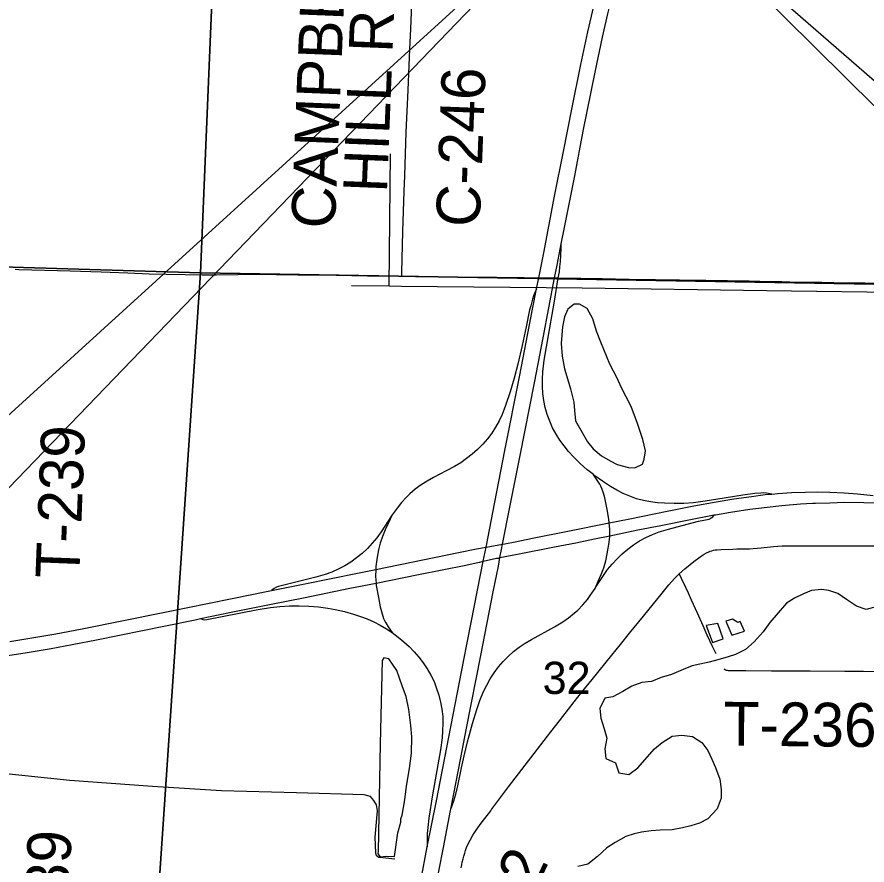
# Model space of a CAD drawing. Extents: x -59 to 43, y 0 to 22.
# Drawn here: x 25.998 to 27.1, y 15.494 to 16.594 of the extents above; entities that cross this region are included whole.
import ezdxf

# ---------------------------------------------------------------- set-up
doc = ezdxf.new("R2010")
doc.units = 0
for name, color, linetype in [('BR_P_Gen_Text', 7, 'Continuous'), ('GM_X_County_Road', 7, 'Continuous'), ('GM_X_County_Road_Text', 7, 'Continuous'), ('GM_X_Interchange_Ramps', 7, 'Continuous'), ('GM_X_Interstate_Route', 7, 'Continuous'), ('GM_X_Major_River', 7, 'Continuous'), ('GM_X_Minor_Lake', 7, 'Continuous'), ('GM_X_Minor_River', 7, 'Continuous'), ('GM_X_Section', 7, 'Continuous'), ('GM_X_Section_Text', 7, 'Continuous'), ('GM_X_Township_Road', 7, 'Continuous'), ('GM_X_Township_Road_Text', 7, 'Continuous'), ('GM_X_US_Route', 7, 'Continuous')]:
    doc.layers.add(name, color=color, linetype=linetype)

msp = doc.modelspace()

# ---------------------------------------------------------------- linework, layer by layer
at = {"layer": 'BR_P_Gen_Text'}
for points in [[(26.7273, 16.7521), (23.5585, 13.8664), (23.9482, 13.8664)], [(26.8361, 16.7501), (30.1526, 13.8664), (29.75, 13.8664)]]:
    msp.add_lwpolyline(points, close=True, dxfattribs=at)
at = {"layer": 'GM_X_County_Road'}
msp.add_line((25.9954, 16.2669), (26.0005, 16.2667), dxfattribs=at)
for points in [[(26.4971, 16.2578), (26.4972, 16.2627), (26.4982, 16.3159), (26.5002, 16.3681), (26.5009, 16.3879), (26.5013, 16.4022), (26.5019, 16.4165), (26.5028, 16.4445), (26.5051, 16.4991), (26.5064, 16.5314), (26.5074, 16.5525), (26.5085, 16.5786), (26.5113, 16.6444), (26.5126, 16.6724), (26.5133, 16.6897), (26.5147, 16.7251), (26.5158, 16.7468), (26.516, 16.7521), (26.5163, 16.7562)], [(26.0005, 16.2667), (26.0171, 16.266), (26.0668, 16.2647), (26.1073, 16.2633), (26.1415, 16.2622), (26.1694, 16.2611), (26.1912, 16.2605), (26.2161, 16.2599), (26.2379, 16.2594), (26.2565, 16.2595), (26.2845, 16.2601), (26.3032, 16.2603), (26.3343, 16.2599), (26.3622, 16.2598), (26.412, 16.2592), (26.4524, 16.2584), (26.4971, 16.2578)], [(26.4971, 16.2578), (26.5147, 16.2576), (26.5427, 16.2575), (26.5675, 16.2571), (26.6204, 16.2565), (26.6483, 16.2561), (26.6555, 16.256)], [(26.6555, 16.256), (26.6747, 16.2559), (26.6952, 16.2556), (26.7, 16.2556), (26.7121, 16.2554)], [(26.7121, 16.2554), (26.7292, 16.2552), (26.75, 16.2548)], [(26.75, 16.2548), (26.7569, 16.2547), (26.7918, 16.2542), (26.826, 16.2536), (26.8571, 16.2531), (26.8913, 16.2525), (26.9473, 16.2517), (26.9753, 16.2511), (26.9897, 16.2508), (27.0002, 16.2507), (27.0418, 16.25), (27.0728, 16.2492), (27.0976, 16.2491), (27.1254, 16.2487), (27.1564, 16.2484), (27.2188, 16.2477)]]:
    msp.add_lwpolyline(points, dxfattribs=at)
at = {"layer": 'GM_X_Interchange_Ramps'}
for points in [[(26.7, 16.2556), (26.7013, 16.2635), (26.7021, 16.2702), (26.7027, 16.2768), (26.7032, 16.2847), (26.7037, 16.2944), (26.7038, 16.3)], [(26.9771, 15.9752), (26.9698, 15.9764), (26.9666, 15.9766), (26.9628, 15.9765), (26.9548, 15.9759), (26.9394, 15.9739), (26.9149, 15.97), (26.8904, 15.9659), (26.8751, 15.9639), (26.8627, 15.963), (26.8503, 15.9629), (26.8379, 15.9632), (26.8287, 15.9638), (26.8194, 15.9649), (26.8103, 15.9667), (26.8013, 15.9691), (26.7926, 15.9723), (26.7841, 15.976), (26.7758, 15.9802), (26.7677, 15.9849), (26.7574, 15.9917), (26.7473, 15.999), (26.745, 16.0008), (26.7376, 16.0067), (26.7283, 16.0149), (26.7195, 16.0236), (26.7133, 16.0305), (26.7074, 16.0377), (26.7019, 16.0452), (26.697, 16.0531), (26.6926, 16.0613), (26.6888, 16.0698), (26.6856, 16.0785), (26.6831, 16.0874), (26.6812, 16.0965), (26.6799, 16.1058), (26.6793, 16.115), (26.6793, 16.1243), (26.6799, 16.1336), (26.6818, 16.149), (26.686, 16.1734), (26.6951, 16.2253), (26.7, 16.2556)], [(26.6718, 16.2413), (26.6692, 16.2356), (26.6679, 16.2322), (26.6666, 16.2281), (26.6642, 16.2196), (26.6628, 16.2144), (26.6582, 16.1921), (26.6533, 16.1678), (26.6476, 16.1436), (26.6429, 16.1256), (26.6375, 16.1077), (26.6315, 16.0901), (26.627, 16.0785), (26.6232, 16.0701), (26.6187, 16.0619), (26.6136, 16.0541), (26.608, 16.0467), (26.6019, 16.0397), (26.5953, 16.0331), (26.5883, 16.0269), (26.581, 16.0211), (26.5734, 16.0158), (26.5655, 16.0109), (26.5545, 16.0051), (26.5379, 15.9967), (26.5298, 15.9921), (26.522, 15.987), (26.5145, 15.9815), (26.5074, 15.9755), (26.5029, 15.9712), (26.4967, 15.9643), (26.491, 15.957), (26.4847, 15.9482), (26.4838, 15.9468), (26.4701, 15.9261), (26.4646, 15.9186), (26.4587, 15.9114), (26.4524, 15.9046), (26.4456, 15.8982), (26.4384, 15.8923), (26.4308, 15.8869), (26.4229, 15.882), (26.4146, 15.8777), (26.4061, 15.8739), (26.3974, 15.8708), (26.3855, 15.8672), (26.3614, 15.8612), (26.3372, 15.8554), (26.3347, 15.8544), (26.3316, 15.8528), (26.328, 15.85)], [(26.7666, 15.9211), (26.767, 15.9295), (26.7661, 15.9378), (26.7656, 15.9426), (26.7634, 15.955), (26.7603, 15.9704), (26.7587, 15.9765), (26.7566, 15.9824), (26.7553, 15.9853), (26.7538, 15.988), (26.7502, 15.9932), (26.745, 16.0008)], [(26.4847, 15.9482), (26.4793, 15.9371), (26.4753, 15.9288), (26.4718, 15.9203), (26.469, 15.9115), (26.4668, 15.9026), (26.4651, 15.8935), (26.4634, 15.8813), (26.4633, 15.8775), (26.463, 15.8683), (26.4636, 15.8597)], [(26.5606, 15.5662), (26.5645, 15.5771), (26.5658, 15.5813), (26.567, 15.5857), (26.5697, 15.5968), (26.5746, 15.6199), (26.5779, 15.6356), (26.5823, 15.6537), (26.5889, 15.6777), (26.5943, 15.6956), (26.5984, 15.7074), (26.6031, 15.7189), (26.6071, 15.7273), (26.6116, 15.7355), (26.6167, 15.7433), (26.6222, 15.7508), (26.6283, 15.7579), (26.6349, 15.7646), (26.6419, 15.7707), (26.6493, 15.7764), (26.657, 15.7816), (26.665, 15.7864), (26.695, 15.8029), (26.7057, 15.8094), (26.7133, 15.8147), (26.7206, 15.8205), (26.7253, 15.8247), (26.7318, 15.8314), (26.7378, 15.8385), (26.7415, 15.8435), (26.7476, 15.8527), (26.7484, 15.8538), (26.7585, 15.8696), (26.7639, 15.8772), (26.7698, 15.8844), (26.7761, 15.8913), (26.7829, 15.8978), (26.79, 15.9038), (26.7975, 15.9094), (26.8054, 15.9144), (26.8136, 15.9188), (26.8221, 15.9226), (26.8308, 15.926), (26.8427, 15.9297), (26.8607, 15.9346), (26.8819, 15.9398), (26.8956, 15.9428), (26.8973, 15.9435), (26.8984, 15.9442), (26.9002, 15.9457), (26.902, 15.9481)], [(26.7476, 15.8527), (26.7517, 15.862), (26.7555, 15.8708), (26.7588, 15.8794), (26.7614, 15.8884), (26.7634, 15.8975), (26.7655, 15.9099), (26.7666, 15.9195), (26.7666, 15.9211)], [(26.4636, 15.8597), (26.4639, 15.8564), (26.4666, 15.841), (26.4691, 15.8288), (26.4714, 15.8197), (26.4734, 15.8138), (26.4746, 15.811), (26.4761, 15.8082), (26.4795, 15.803), (26.4844, 15.7954)], [(26.2358, 15.8136), (26.2389, 15.8123), (26.2415, 15.812), (26.2441, 15.8124), (26.3082, 15.825), (26.3266, 15.8279), (26.339, 15.8293), (26.3515, 15.83), (26.3639, 15.8301), (26.3764, 15.8297), (26.3888, 15.8287), (26.4012, 15.827), (26.4104, 15.8254), (26.4225, 15.8226), (26.4345, 15.8193), (26.4434, 15.8164), (26.4521, 15.8131), (26.4607, 15.8092), (26.469, 15.805), (26.477, 15.8002), (26.4844, 15.7954), (26.4924, 15.7895), (26.4996, 15.7836), (26.5065, 15.7773), (26.5129, 15.7705), (26.519, 15.7634), (26.5247, 15.756), (26.53, 15.7483), (26.5346, 15.7402), (26.5388, 15.7318), (26.5422, 15.7231), (26.5452, 15.7142), (26.5474, 15.7052), (26.549, 15.696), (26.55, 15.6867), (26.5503, 15.6773), (26.5499, 15.668), (26.5492, 15.6587), (26.547, 15.6433), (26.5369, 15.5849), (26.5321, 15.5547), (26.5308, 15.5426), (26.5301, 15.5347), (26.53, 15.5279), (26.5301, 15.5175)]]:
    msp.add_lwpolyline(points, dxfattribs=at)
at = {"layer": 'GM_X_Interstate_Route'}
for points in [[(26.7038, 16.3), (26.7079, 16.3211), (26.7213, 16.3882), (26.7323, 16.4462), (26.7476, 16.5224), (26.7572, 16.5681), (26.7642, 16.5984), (26.7724, 16.6316), (26.7805, 16.6616), (26.7992, 16.7274), (26.8026, 16.7393), (26.8049, 16.7469)], [(26.6718, 16.2413), (26.6747, 16.2559), (26.6811, 16.2883), (26.6952, 16.3616), (26.7067, 16.4195), (26.7174, 16.4745), (26.729, 16.5324), (26.7383, 16.5749), (26.7461, 16.6082)], [(26.6952, 16.2556), (26.6984, 16.2723), (26.7038, 16.3)], [(26.6222, 15.8818), (26.6243, 15.8927), (26.6263, 15.9032), (26.6277, 15.9102), (26.6372, 15.9581), (26.6503, 16.0252), (26.6689, 16.1197), (26.6803, 16.1777), (26.6952, 16.2556)], [(26.5301, 15.5175), (26.5418, 15.5773), (26.5579, 15.6596), (26.5776, 15.7603), (26.5913, 15.8305), (26.6026, 15.888), (26.6062, 15.9062), (26.6176, 15.9647), (26.6307, 16.0318), (26.6499, 16.1294), (26.6583, 16.1721), (26.6666, 16.2149), (26.6718, 16.2413)], [(26.551, 15.5166), (26.5603, 15.5645), (26.5606, 15.5662), (26.5709, 15.6195), (26.5808, 15.6714), (26.5996, 15.7659), (26.6157, 15.8483), (26.6222, 15.8818)], [(26.4474, 15.0879), (26.448, 15.092), (26.4521, 15.1165), (26.4637, 15.1776), (26.4776, 15.2489), (26.4839, 15.2813), (26.5036, 15.382), (26.5215, 15.4735), (26.5301, 15.5175)], [(26.5402, 15.4616), (26.5456, 15.4882), (26.551, 15.5166)]]:
    msp.add_lwpolyline(points, dxfattribs=at)
at = {"layer": 'GM_X_Major_River'}
for points in [[(27.1087, 15.8281), (27.0991, 15.8256), (27.0867, 15.8296), (27.0739, 15.8382), (27.0623, 15.846), (27.0509, 15.85), (27.0415, 15.8513), (27.0285, 15.8501), (27.0178, 15.8457), (27.0063, 15.8402), (26.9959, 15.8335), (26.9851, 15.8212), (26.9742, 15.8085), (26.9656, 15.7965), (26.954, 15.7834), (26.9428, 15.7733), (26.9297, 15.7671), (26.9202, 15.7642), (26.9068, 15.7599), (26.8954, 15.7571), (26.8835, 15.7543), (26.8736, 15.7525), (26.8617, 15.7474), (26.8468, 15.7409), (26.8334, 15.7373), (26.8208, 15.7322)], [(26.8208, 15.7322), (26.8082, 15.7305), (26.7952, 15.7258), (26.7837, 15.7192), (26.7707, 15.7122), (26.7604, 15.7105), (26.7537, 15.6969), (26.755, 15.6844), (26.7593, 15.6706), (26.7629, 15.6584), (26.7603, 15.6448), (26.7616, 15.6322), (26.7741, 15.6263), (26.7784, 15.6133), (26.7913, 15.6112), (26.8032, 15.6201), (26.8249, 15.6448), (26.8346, 15.653), (26.8476, 15.6611), (26.8602, 15.6624), (26.8739, 15.6606), (26.8863, 15.6528), (26.894, 15.6424), (26.8992, 15.6313), (26.9039, 15.6206), (26.9093, 15.6053), (26.911, 15.5919), (26.9112, 15.5805), (26.906, 15.5666), (26.894, 15.5539), (26.8829, 15.548), (26.8718, 15.5448), (26.8611, 15.5423), (26.8477, 15.5395), (26.8321, 15.539), (26.8203, 15.5381), (26.8078, 15.5364), (26.7982, 15.5343), (26.7875, 15.5307), (26.7737, 15.523), (26.7629, 15.516), (26.7506, 15.5048), (26.7382, 15.4951), (26.7253, 15.4919)]]:
    msp.add_lwpolyline(points, dxfattribs=at)
at = {"layer": 'GM_X_Minor_Lake'}
for p, q in [((26.7224, 16.0702), (26.7379, 16.0428)), ((26.9172, 15.8103), (26.9251, 15.7922)), ((26.9069, 15.8074), (26.8917, 15.8046))]:
    msp.add_line(p, q, dxfattribs=at)
for points in [[(26.7379, 16.0428), (26.7453, 16.0337), (26.7561, 16.0247), (26.7674, 16.0181), (26.7761, 16.0137), (26.7908, 16.0097), (26.7992, 16.0092), (26.8092, 16.0139), (26.8115, 16.0203), (26.8129, 16.0313), (26.8097, 16.0458), (26.8025, 16.0668), (26.7945, 16.0886), (26.7879, 16.1013), (26.7821, 16.1132), (26.7762, 16.1254), (26.7666, 16.1435), (26.755, 16.1722), (26.7496, 16.1867), (26.7449, 16.2027), (26.7375, 16.2158), (26.7274, 16.2217), (26.7205, 16.2214), (26.7124, 16.2151), (26.7081, 16.2053), (26.7056, 16.192), (26.7037, 16.1704), (26.7049, 16.1541), (26.708, 16.1377), (26.7123, 16.1235), (26.7159, 16.1117), (26.7202, 16.0945), (26.7211, 16.0835), (26.7224, 16.0702)], [(26.9251, 15.7922), (26.9413, 15.7973), (26.9358, 15.8099), (26.9328, 15.8085), (26.926, 15.8128), (26.9172, 15.8103)], [(26.8917, 15.8046), (26.8998, 15.7828), (26.9139, 15.7872), (26.9069, 15.8074)], [(26.4904, 15.7462), (26.4851, 15.7546), (26.4802, 15.7614), (26.4737, 15.7626), (26.4714, 15.7592), (26.4688, 15.6509), (26.4665, 15.5119), (26.4661, 15.5085), (26.4688, 15.5046), (26.4771, 15.5054), (26.4874, 15.505)], [(26.4874, 15.505), (26.4919, 15.5356), (26.4957, 15.5493), (26.4957, 15.5536), (26.4973, 15.5585), (26.5011, 15.5784), (26.5033, 15.5962), (26.5068, 15.6189), (26.5094, 15.639), (26.5098, 15.6603), (26.5089, 15.6747), (26.5062, 15.6957), (26.5027, 15.7125), (26.4977, 15.7251), (26.4934, 15.7374), (26.4904, 15.7462)]]:
    msp.add_lwpolyline(points, dxfattribs=at)
at = {"layer": 'GM_X_Minor_River'}
for points in [[(26.4805, 16.2447), (26.4822, 16.4164)], [(26.4968, 16.2443), (26.4805, 16.2447), (26.4316, 16.2452)], [(27.6072, 16.2249), (27.5149, 16.2285), (27.2969, 16.2339), (27.1651, 16.2362), (26.9698, 16.239), (26.7308, 16.2425), (26.4968, 16.2443)], [(26.4881, 15.5016), (26.4722, 15.5031), (26.4672, 15.5035), (26.4642, 15.5058), (26.4635, 15.5096), (26.4624, 15.5301), (26.4655, 15.5643), (26.4644, 15.5719), (26.4606, 15.5776), (26.4565, 15.5826), (26.4481, 15.5849), (26.3605, 15.5874), (26.263, 15.5903), (26.1735, 15.5959), (26.0665, 15.6035), (25.9796, 15.6128)]]:
    msp.add_lwpolyline(points, dxfattribs=at)
at = {"layer": 'GM_X_Section'}
for points in [[(25.1878, 17.2935), (26.2782, 17.275), (26.2361, 16.2622), (25.1744, 16.294), (25.173, 16.308)], [(27.273, 17.253), (27.2374, 16.2454), (26.2361, 16.2622), (26.2782, 17.275)], [(25.1744, 16.294), (26.2361, 16.2622), (26.1685, 15.2661), (25.1667, 15.3001)], [(26.2361, 16.2622), (27.2374, 16.2454), (27.2021, 15.2348), (26.2022, 15.2649), (26.1685, 15.2661)]]:
    msp.add_lwpolyline(points, close=True, dxfattribs=at)
at = {"layer": 'GM_X_Township_Road'}
for points in [[(26.9315, 15.9039), (26.9425, 15.904), (26.948, 15.9042), (26.9526, 15.9044), (26.9631, 15.9053), (26.9792, 15.907), (26.9903, 15.9078), (27.0034, 15.9081), (27.0469, 15.9081), (27.0979, 15.9081), (27.152, 15.9081)], [(26.8567, 15.8716), (26.8639, 15.878), (26.8759, 15.8878), (26.8839, 15.8937), (26.8891, 15.8972), (26.8923, 15.899), (26.8952, 15.9003), (26.897, 15.901), (26.899, 15.9017), (26.9011, 15.9023), (26.9033, 15.9027), (26.9062, 15.903), (26.9113, 15.9033), (26.9265, 15.9038), (26.9315, 15.9039)], [(26.6135, 15.566), (26.6355, 15.5952), (26.6904, 15.6667), (26.7015, 15.6809), (26.7205, 15.7055), (26.7302, 15.7176), (26.744, 15.7345), (26.7692, 15.7661), (26.7805, 15.7801), (26.7923, 15.7946), (26.8105, 15.8167), (26.8346, 15.8467), (26.8433, 15.8573), (26.8508, 15.8656), (26.8542, 15.8691), (26.8567, 15.8716)], [(26.8567, 15.8716), (26.8594, 15.8662), (26.865, 15.8544), (26.8683, 15.847), (26.8721, 15.8379), (26.8799, 15.821), (26.8874, 15.8046), (26.8926, 15.7927), (26.899, 15.7786), (26.9041, 15.7681)], [(26.9145, 15.7484), (26.9155, 15.7478), (26.9166, 15.7473), (26.9176, 15.7469), (26.9188, 15.7466), (26.9202, 15.7464), (26.9219, 15.7463), (26.9287, 15.7462), (26.9432, 15.7462), (26.9766, 15.746), (27.0266, 15.7457), (27.0717, 15.7455), (27.0959, 15.7453), (27.1251, 15.7451), (27.1869, 15.7445), (27.2147, 15.7442), (27.2495, 15.7436), (27.2712, 15.7429), (27.2805, 15.7425), (27.2894, 15.7422), (27.319, 15.7418), (27.4098, 15.7395), (27.4626, 15.738), (27.4747, 15.7376)], [(26.5742, 15.4903), (26.5748, 15.494), (26.5755, 15.4976), (26.5764, 15.5017), (26.5774, 15.5055), (26.5786, 15.5092), (26.5797, 15.5126), (26.5811, 15.5164), (26.5824, 15.5195), (26.5856, 15.5262), (26.5893, 15.5327), (26.5934, 15.539), (26.6, 15.548), (26.6123, 15.5644), (26.6135, 15.566)]]:
    msp.add_lwpolyline(points, dxfattribs=at)
at = {"layer": 'GM_X_US_Route'}
for points in [[(25.9888, 15.7841), (26.0225, 15.7895), (26.0483, 15.7939), (26.0825, 15.8003), (26.1874, 15.8213), (26.2769, 15.8398), (26.3214, 15.8487), (26.328, 15.85), (26.3713, 15.8589), (26.4396, 15.8727), (26.4633, 15.8775), (26.5706, 15.8992), (26.5937, 15.9039), (26.6062, 15.9062), (26.6277, 15.9102), (26.6308, 15.9108), (26.6442, 15.9133), (26.6667, 15.9178), (26.7124, 15.9272), (26.7661, 15.9378), (26.7905, 15.9427), (26.8435, 15.9534), (26.8758, 15.9597), (26.9045, 15.965), (26.9278, 15.9689), (26.9506, 15.9722), (26.9684, 15.9744), (26.9771, 15.9752), (26.9845, 15.9759), (27.0025, 15.9771), (27.0204, 15.9778), (27.036, 15.978), (27.0521, 15.9776), (27.0707, 15.9767), (27.088, 15.9753), (27.1084, 15.9731)], [(26.62, 15.8918), (26.6219, 15.8922), (26.6243, 15.8927), (26.6494, 15.8978), (26.6952, 15.9065), (26.7226, 15.912), (26.747, 15.917), (26.7666, 15.9211), (26.803, 15.9286), (26.8329, 15.9345), (26.8694, 15.9419), (26.902, 15.9481), (26.9037, 15.9484), (26.9233, 15.9517), (26.9485, 15.9554), (26.9708, 15.9582), (26.99, 15.9602), (27.0142, 15.9623), (27.0298, 15.9632)], [(27.0298, 15.9632), (27.0337, 15.9635), (27.0519, 15.964), (27.071, 15.9645), (27.1462, 15.9634)], [(26.1906, 15.8044), (26.229, 15.8122), (26.2358, 15.8136), (26.2734, 15.8213), (26.3277, 15.8322), (26.3697, 15.8407), (26.4294, 15.8529), (26.4636, 15.8597), (26.5185, 15.8706), (26.58, 15.8831), (26.5972, 15.8868)], [(26.5972, 15.8868), (26.5982, 15.887), (26.6026, 15.888), (26.62, 15.8918)], [(25.986, 15.7659), (26.0112, 15.7697), (26.0424, 15.775), (26.0693, 15.7799), (26.101, 15.7862), (26.1906, 15.8044)]]:
    msp.add_lwpolyline(points, dxfattribs=at)

# ---------------------------------------------------------------- texts
at = {"layer": 'GM_X_County_Road_Text'}
for s, rotation, p in [('CAMPBELL', 87.6885, (26.4102, 16.3189)), ('HILL RD', 87.7323, (26.4777, 16.3657)), ('C-246', 87.7975, (26.5979, 16.3209))]:
    msp.add_text(s, height=0.05682, rotation=rotation, dxfattribs=at).set_placement(p)
at = {"layer": 'GM_X_Section_Text'}
msp.add_text('32', height=0.04186, rotation=0, dxfattribs=at).set_placement((26.6796, 15.7158))
at = {"layer": 'GM_X_Township_Road_Text'}
for s, height, rotation, p in [('T-239', 0.05682, 87.7558, (26.0786, 15.8648)), ('T-236', 0.05682, 359.4415, (26.914, 15.6489)), ('T-239', 0.05682, 87.1962, (26.0594, 15.3394)), ('2', 0.0568, 65.0293, (26.6702, 15.4594))]:
    msp.add_text(s, height=height, rotation=rotation, dxfattribs=at).set_placement(p)

doc.saveas('drawing.dxf')
